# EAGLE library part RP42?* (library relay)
Power PCB Relay RP II/2 Schrack 2 pole 8 A Source: http://www.schrack.com/.. 5844.pdf
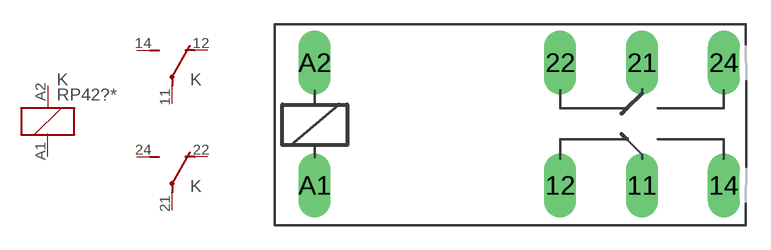
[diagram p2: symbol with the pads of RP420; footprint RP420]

Designator prefix K; gates 1=K 2=U 3=U

## RP420005 (MPN: RP420005; OC_FARNELL: unknown; OC_NEWARK: 48M7798), RP420006 (MPN: RP420006; OC_FARNELL: unknown; OC_NEWARK: 48M7799), RP420012 (MF: TYCO ELECTRONICS; MPN: RP420012; OC_FARNELL: 3103330; OC_NEWARK: 90B4410), RP420024 (MF: TYCO ELECTRONICS; MPN: RP420024; OC_FARNELL: 1703720; OC_NEWARK: 51B969), RP420048 (MF: TYCO ELECTRONICS; MPN: RP420048; OC_FARNELL: unknown; OC_NEWARK: 92C3381), RP420060 (MPN: RP420060; OC_FARNELL: unknown; OC_NEWARK: 48M7803), RP420110 (MF: TYCO ELECTRONICS; MPN: RP420110; OC_FARNELL: unknown; OC_NEWARK: 08H3601)  [RP420]
11  2:P  pas
12  2:O  pas
14  2:S  pas
21  3:P  pas
22  3:O  pas
24  3:S  pas
A1  1:2  pas
A2  1:1  pas

## RP421005 (MF: TYCO ELECTRONICS; MPN: 6-1393234-4; OC_FARNELL: unknown; OC_NEWARK: 16H0760), RP421006 (MF: TYCO ELECTRONICS; MPN: 6-1393234-5; OC_FARNELL: unknown; OC_NEWARK: 16H0761), RP421012 (MF: TYCO ELECTRONICS; MPN: RP421012; OC_FARNELL: unknown; OC_NEWARK: 90B5481), RP421024 (MF: TYCO ELECTRONICS; MPN: RP421024; OC_FARNELL: 1608388; OC_NEWARK: 01C0518), RP421048 (MF: TYCO ELECTRONICS; MPN: RP421048; OC_FARNELL: unknown; OC_NEWARK: 08H3604), RP421060 (MF: TYCO ELECTRONICS; MPN: RP421060; OC_FARNELL: unknown; OC_NEWARK: 84H0645), RP421110 (MF: TYCO ELECTRONICS; MPN: RP421110; OC_FARNELL: unknown; OC_NEWARK: 39C2625)  [RP420]
Pads as for RP420

## Footprint RP420 (pad centres in mm)
RELAY 2 x switch, Schrack
drill 1.321 long: 11 16.51,-3.81; 12 11.43,-3.81; 14 21.59,-3.81; 21 16.51,3.81; 22 11.43,3.81; 24 21.59,3.81; A1 -3.81,-3.81; A2 -3.81,3.81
